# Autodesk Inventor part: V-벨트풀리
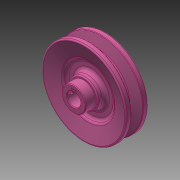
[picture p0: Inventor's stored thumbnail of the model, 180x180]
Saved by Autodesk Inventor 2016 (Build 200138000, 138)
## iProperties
Created: 2016-08
Part Number: V-벨트풀리
Material: 알루미늄 6061
Document SubType Name: Modeling
Designer: mduedu
Density: 2.71 g/cm^3
Appearance: 분홍색
Author: mduedu
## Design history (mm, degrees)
sketch "스케치1"
  geometry: L1 (0, 17.5)-(0, -9.5); L2 (10, 9.5)-(35, 9.5); L3 (35, 9.5)-(35, 4.825); L4 (35, 4.825)-(26, 2.074); L5 (26, 2.074)-(26, 0); L6 (0, 0)-(26, 0); L7 (0, -9.5)-(35, -9.5); L8 (35, -9.5)-(35, -4.825); L9 (35, -4.825)-(26, -2.074); L10 (26, -2.074)-(26, 0); L11 (32.3, 9.5)-(32.3, -9.5); L12 (10, 9.5)-(10, 17.5); L13 (10, 17.5)-(0, 17.5); 3 further points
  constraints: 26 end point, 7 point on line, 5 perpendicular, 3 symmetric about line, 2 parallel, 1 coincident, 1 horizontal alignment, 1 vertical
  dimensions: "d2" = 70 diameter of L8 L1; "d4" = 6.3 distance between parallel lines of L10 L11; "d5" = 2.7 distance between parallel lines of L11 L8; "d6" = 8 distance of point (32.3, -4) point (32.3, 4); "d7" = 34 deg angle of L9 L4; "d30" = 9.5 distance between parallel lines of L7 L6; "d32" = 27 distance between parallel lines of L13 L7; "d33" = 20 diameter of L12 L1
revolve "회전1" sketch "스케치1" stored, may be unused: angle "d8" = 90 deg
sketch "스케치2"
  geometry: L1 (-2, 0)-(2, 0); L2 (2, 0)-(2, 7.3); L3 (2, 7.3)-(-2, 7.3); L4 (-2, 7.3)-(-2, 0); C1 r 5.5 at (0, 0); 2 further points
  constraints: 8 end point, 2 coincident, 2 parallel, 1 centre point, 1 horizontal, 1 midpoint, 1 perpendicular
  dimensions: "d9" = 11 diameter of C1; "d11" = 4 distance of L2.end L3.end; "d34" = 12.8 dimension on C1 L3
extrude "돌출1" cut sketch "스케치2" stored distance "d13" = 10; taper "d14" = 0 deg
sketch "스케치3"
  geometry: L1 (35, 4.825)-(26, 2.074) reference; L2 (26, 2.074)-(26, -2.074) reference; L3 (0, 0)-(26, 0); L4 (35, 9.5)-(35, 4.825) reference; L5 (-35, 9.5)-(35, 9.5) reference; L6 (35, 9.5)-(21, 5.22); L7 (21, 5.22)-(21, 3); L8 (21, 3)-(12, 3); L9 (12, 3)-(12, 9.5); L10 (0, 9.5)-(0, -9.5); L11 (5.123, -9.5)-(-5.5, -9.5) reference; L12 (12, 9.5)-(35, 9.5)
  constraints: 14 end point, 3 midpoint, 2 parallel, 2 perpendicular, 2 point on line, 1 collinear, 1 horizontal
  dimensions: "d15" = 3 distance between parallel lines of L3 L8; "d17" = 42 diameter of L7 L10; "d18" = 24 diameter of L9 L10
revolve "회전2" sketch "스케치3" stored, may be unused: angle "d19" = 90 deg
fillet "모깎기1" dims "d20" = 0.5, "d21" = 1, "d22" = 1
fillet "모깎기2" dims "d23" = 3
fillet "모깎기3" dims "d24" = 3
fillet "모깎기4" dims "d25" = 3
chamfer "모따기1" distance "d26" = 0.5; stored, may be unused: second distance "d27" = 2, angle "d28" = 45 deg
fillet "모깎기5" dims "d29" = 1
node "작업 평면1"
sketch "스케치4"
  geometry: L1 (-9.5, 17.5)-(9.5, 17.5) reference; 2 further points
  constraints: 1 vertical alignment
  dimensions: "d41" = 4 distance from line of L1 point (0, 13.5)
hole "구멍1" sketch "스케치4" at (0, 13.5) diameter "d42" = 2.459; stored, may be unused: countersink angle "d46" = 90 deg, drill point angle "d48" = 118 deg; dims "d43" = 6, "d44" = 4, "d45" = 2, "d47" = 8
node "솔리드1"
mirror "대칭1"
